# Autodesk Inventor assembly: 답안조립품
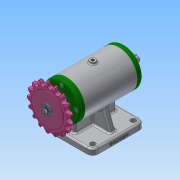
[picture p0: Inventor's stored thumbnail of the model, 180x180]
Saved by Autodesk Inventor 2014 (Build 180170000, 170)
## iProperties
Created: 2019-06
Part Number: 답안조립품
Document SubType Name: Assembly
Designer: user
Author: user
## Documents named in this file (11)
- C:\Users\user\Desktop\490604V1011\답안조립품.iam
- C:\Users\user\Desktop\490604V1011\본체.ipt
- C:\Users\user\Desktop\490604V1011\베어링 6203.ipt
- C:\Users\user\Desktop\490604V1011\볼트 M4.ipt
- C:\Users\user\Desktop\490604V1011\스프로킷.ipt
- C:\Users\user\Desktop\490604V1011\스프링와셔.ipt
- C:\Users\user\Desktop\490604V1011\오일 실 17 30 5.ipt
- C:\Users\user\Desktop\490604V1011\축.ipt
- C:\Users\user\Desktop\490604V1011\커버.ipt
- C:\Users\user\Desktop\490604V1011\키 4x4x12.ipt
- C:\Users\user\Desktop\490604V1011\평와셔.ipt
